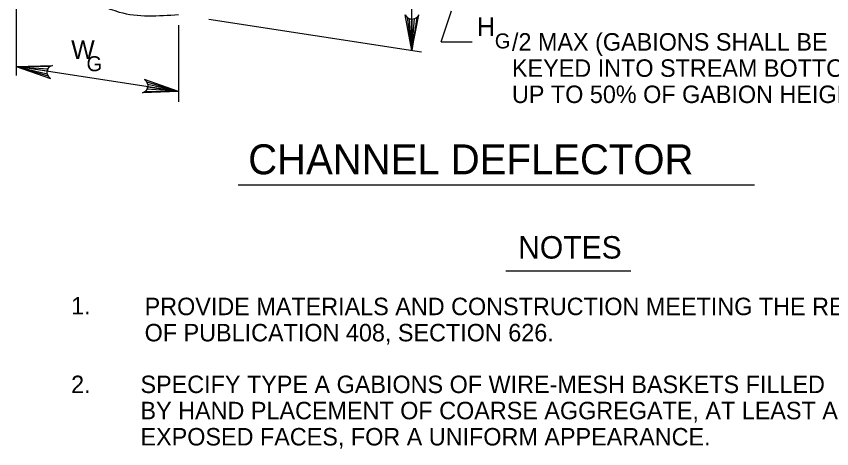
# Model space of a CAD drawing. Extents: x 3 to 3592, y -602 to 1171.
# Drawn here: x 590.1 to 753.3, y 928 to 1014.6 of the extents above; entities that cross this region are included whole.
import ezdxf

# ---------------------------------------------------------------- set-up
doc = ezdxf.new("R2010")
doc.units = 0
doc.layers.add('2', color=7, linetype='Continuous')
doc.layers.add('3', color=7, linetype='Continuous')

msp = doc.modelspace()

# ---------------------------------------------------------------- linework, layer by layer
at = {"layer": '2'}
for p, q in [((669.3, 1007.82), (669.3, 1026.57)), ((590.06, 1017.95), (590.06, 1002.81)), ((675.16, 1009.53), (677.19, 1015.73)), ((628.63, 1014.08), (671.21, 1007.53)), ((622.56, 1012.9), (622.56, 997.49)), ((675.16, 1009.53), (681.38, 1009.53)), ((622.56, 999.58), (590.06, 1004.58))]:
    msp.add_line(p, q, dxfattribs=at)
for points in [[(669.3, 1007.82), (667.96, 1014.95), (668.35, 1014.4), (669.3, 1007.82), (668.82, 1014.12), (669.3, 1014.04), (669.3, 1007.82), (669.78, 1014.12), (670.26, 1014.4), (669.3, 1007.82), (670.64, 1014.95), (670.26, 1014.4), (669.78, 1014.12), (669.3, 1014.04), (668.82, 1014.12), (668.35, 1014.4)], [(590.06, 1004.58), (597.31, 1004.82), (596.71, 1004.53), (590.06, 1004.58), (596.36, 1004.1), (596.21, 1003.64), (590.06, 1004.58), (596.21, 1003.15), (596.42, 1002.63), (590.06, 1004.58), (596.91, 1002.18), (596.42, 1002.63), (596.21, 1003.15), (596.21, 1003.64), (596.36, 1004.1), (596.71, 1004.53)], [(622.56, 999.58), (615.31, 999.34), (615.91, 999.64), (622.56, 999.58), (616.26, 1000.07), (616.42, 1000.53), (622.56, 999.58), (616.41, 1001.01), (616.2, 1001.53), (622.56, 999.58), (615.72, 1001.99), (616.2, 1001.53), (616.41, 1001.01), (616.42, 1000.53), (616.26, 1000.07), (615.91, 999.64)]]:
    msp.add_lwpolyline(points, dxfattribs=at)
msp.add_spline([(590.06, 1020.01), (595.15, 1019.27), (603.61, 1018.09), (610.65, 1015.51), (622.56, 1015.01)], degree=3, dxfattribs=at)
at = {"layer": '3'}
for p, q in [((634.5, 980.88), (737.92, 980.88)), ((688.12, 963.66), (713.11, 963.66))]:
    msp.add_line(p, q, dxfattribs=at)

# ---------------------------------------------------------------- texts
for s, height, p in [('H', 3.75, (682.29, 1010.72)), ('G', 3, (685.88, 1008.21)), ('/2 MAX (GABIONS SHALL BE', 3.5, (689.32, 1007.77)), ('W', 3.75, (601.04, 1006.11)), ('G', 3, (604.12, 1003.65)), ('KEYED INTO STREAM BOTTOM', 3.5, (689.32, 1002.52)), ('UP TO 50% OF GABION HEIGHT).', 3.5, (689.32, 997.27)), ('CHANNEL DEFLECTOR', 6, (636.5, 982.99)), ('NOTES', 4.5, (690.56, 966.1)), ('1.  ', 3.5, (601.04, 954.9)), ('PROVIDE MATERIALS AND CONSTRUCTION MEETING THE REQUIREMENTS', 3.5, (615.76, 954.76)), ('OF PUBLICATION 408, SECTION 626.', 3.5, (615.76, 949.51)), ('2.  ', 3.5, (601.04, 939.15)), ('SPECIFY TYPE A GABIONS OF WIRE-MESH BASKETS FILLED', 3.5, (614.93, 939.15)), ('BY HAND PLACEMENT OF COARSE AGGREGATE, AT LEAST ALONG THE', 3.5, (614.93, 933.9)), ('EXPOSED FACES, FOR A UNIFORM APPEARANCE.', 3.5, (614.93, 928.65))]:
    msp.add_text(s, height=height, dxfattribs=at).set_placement(p)

doc.saveas('drawing.dxf')
